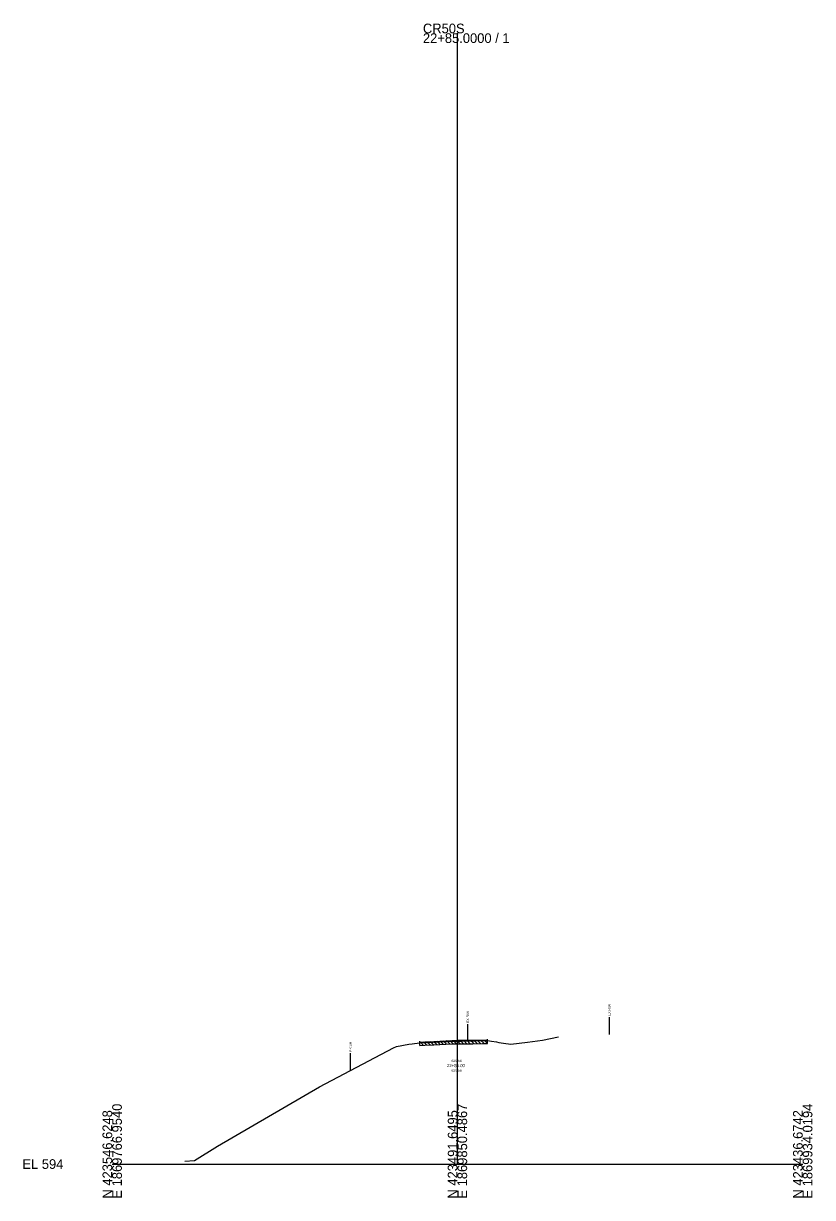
# Model space of a CAD drawing. Extents: x 1866342 to 1870084, y 421982 to 426629.
# Drawn here: x 1866342.4 to 1866571, y 421981.9 to 422321.8 of the extents above; entities that cross this region are included whole.
import ezdxf

# ---------------------------------------------------------------- set-up
doc = ezdxf.new("R2010")
doc.units = 0
for name, color, linetype in [('GK_Cells', 7, 'Continuous'), ('RW_P_Esmt_SH', 7, 'Continuous'), ('RW_X_Fee_RW', 7, 'Continuous'), ('XS_P_Annotation', 7, 'Continuous'), ('XS_X_Ground_Line', 7, 'Continuous'), ('XS_X_Pavt', 7, 'Continuous')]:
    doc.layers.add(name, color=color, linetype=linetype)

msp = doc.modelspace()

# ---------------------------------------------------------------- linework, layer by layer
at = {"layer": 'GK_Cells'}
for p, q in [((1866468.12, 421991.63), (1866468.12, 422318.98)), ((1866368.12, 421991.63), (1866468.12, 421991.63)), ((1866468.12, 421991.63), (1866568.12, 421991.63))]:
    msp.add_line(p, q, dxfattribs=at)
at = {"layer": 'RW_P_Esmt_SH'}
msp.add_line((1866437.12, 422018.72), (1866437.12, 422023.72), dxfattribs=at)
at = {"layer": 'RW_X_Fee_RW'}
for p, q in [((1866512.12, 422029.18), (1866512.12, 422034.18)), ((1866471.12, 422027.17), (1866471.12, 422032.17))]:
    msp.add_line(p, q, dxfattribs=at)
at = {"layer": 'XS_X_Ground_Line'}
msp.add_lwpolyline([(1866389.18, 421992.49), (1866391.92, 421992.63), (1866398.66, 421996.78), (1866428.15, 422013.99), (1866449.57, 422025.29), (1866450.43, 422025.69), (1866454.02, 422026.3), (1866455.05, 422026.45), (1866457.1, 422026.68), (1866465.04, 422027.08), (1866466.99, 422027.19), (1866468.12, 422027.2), (1866469.23, 422027.2), (1866476.79, 422027.37), (1866478.01, 422027.18), (1866479.42, 422027.02), (1866480.12, 422026.85), (1866481.43, 422026.64), (1866483.58, 422026.3), (1866488.4, 422026.9), (1866492.78, 422027.46), (1866497.35, 422028.47)], dxfattribs=at)
at = {"layer": 'XS_X_Pavt'}
for p, q in [((1866457.21, 422026.94), (1866457.21, 422027.19)), ((1866457.21, 422026.94), (1866458.7, 422027.01)), ((1866457.21, 422025.94), (1866457.21, 422026.94)), ((1866458.32, 422025.99), (1866457.39, 422026.93)), ((1866459.27, 422026.04), (1866458.32, 422026.99)), ((1866458.7, 422027.01), (1866461.23, 422027.15)), ((1866460.22, 422026.1), (1866459.27, 422027.04)), ((1866461.17, 422026.15), (1866460.22, 422027.1)), ((1866462.12, 422026.2), (1866461.17, 422027.15)), ((1866461.23, 422027.15), (1866466.45, 422027.43)), ((1866463.07, 422026.25), (1866462.12, 422027.2)), ((1866464.02, 422026.3), (1866463.07, 422027.25)), ((1866464.97, 422026.35), (1866464.02, 422027.3)), ((1866465.92, 422026.4), (1866464.97, 422027.35)), ((1866466.88, 422026.44), (1866465.92, 422027.4)), ((1866466.45, 422027.43), (1866468.12, 422027.45)), ((1866467.87, 422026.45), (1866466.88, 422027.44)), ((1866468.87, 422026.45), (1866467.87, 422027.45)), ((1866468.12, 422027.45), (1866472.56, 422027.48)), ((1866468.12, 422026.45), (1866472.56, 422026.48)), ((1866469.86, 422026.46), (1866468.87, 422027.45)), ((1866470.85, 422026.47), (1866469.86, 422027.46)), ((1866471.84, 422026.48), (1866470.85, 422027.47)), ((1866472.83, 422026.49), (1866471.84, 422027.48)), ((1866472.56, 422027.48), (1866475.4, 422027.5)), ((1866472.56, 422026.48), (1866475.4, 422026.5)), ((1866473.83, 422026.49), (1866472.83, 422027.49)), ((1866474.82, 422026.5), (1866473.83, 422027.49)), ((1866475.81, 422026.51), (1866474.82, 422027.5)), ((1866475.4, 422027.5), (1866476.79, 422027.53)), ((1866475.4, 422026.5), (1866476.79, 422026.53)), ((1866476.79, 422026.53), (1866475.81, 422027.51)), ((1866476.79, 422027.53), (1866476.79, 422027.78)), ((1866476.79, 422026.53), (1866476.79, 422027.53)), ((1866457.21, 422025.94), (1866458.7, 422026.01)), ((1866458.7, 422026.01), (1866461.23, 422026.15)), ((1866461.23, 422026.15), (1866466.45, 422026.43)), ((1866466.45, 422026.43), (1866468.12, 422026.45))]:
    msp.add_line(p, q, dxfattribs=at)

# ---------------------------------------------------------------- texts
at = {"layer": 'GK_Cells'}
for s, p in [('CR50S', (1866458.12, 422318.98)), ('22+85.0000 / 1', (1866458.12, 422316.18)), ('EL 594', (1866342.12, 421990.23))]:
    msp.add_text(s, height=2.8, dxfattribs=at).set_placement(p)
for s, p in [('N 423546.6248', (1866368.12, 421981.63)), ('E 1869766.9540', (1866370.92, 421981.63)), ('N 423491.6495', (1866468.12, 421981.63)), ('E 1869850.4867', (1866470.92, 421981.63)), ('N 423436.6742', (1866568.12, 421981.63)), ('E 1869934.0194', (1866570.92, 421981.63))]:
    msp.add_text(s, height=2.8, rotation=90, dxfattribs=at).set_placement(p)
at = {"layer": 'RW_P_Esmt_SH'}
msp.add_text('PR SH', height=0.7, rotation=90, dxfattribs=at).set_placement((1866437.47, 422024.07))
at = {"layer": 'RW_X_Fee_RW'}
for p in [(1866512.47, 422034.53), (1866471.47, 422032.52)]:
    msp.add_text('EX R/W', height=0.7, rotation=90, dxfattribs=at).set_placement(p)
at = {"layer": 'XS_P_Annotation'}
for s, height, p in [('22+85.00', 0.9, (1866465.07, 422019.68)), ('629.56', 0.7, (1866466.4, 422021.18)), ('629.56', 0.7, (1866466.4, 422018.38))]:
    msp.add_text(s, height=height, dxfattribs=at).set_placement(p)

doc.saveas('drawing.dxf')
